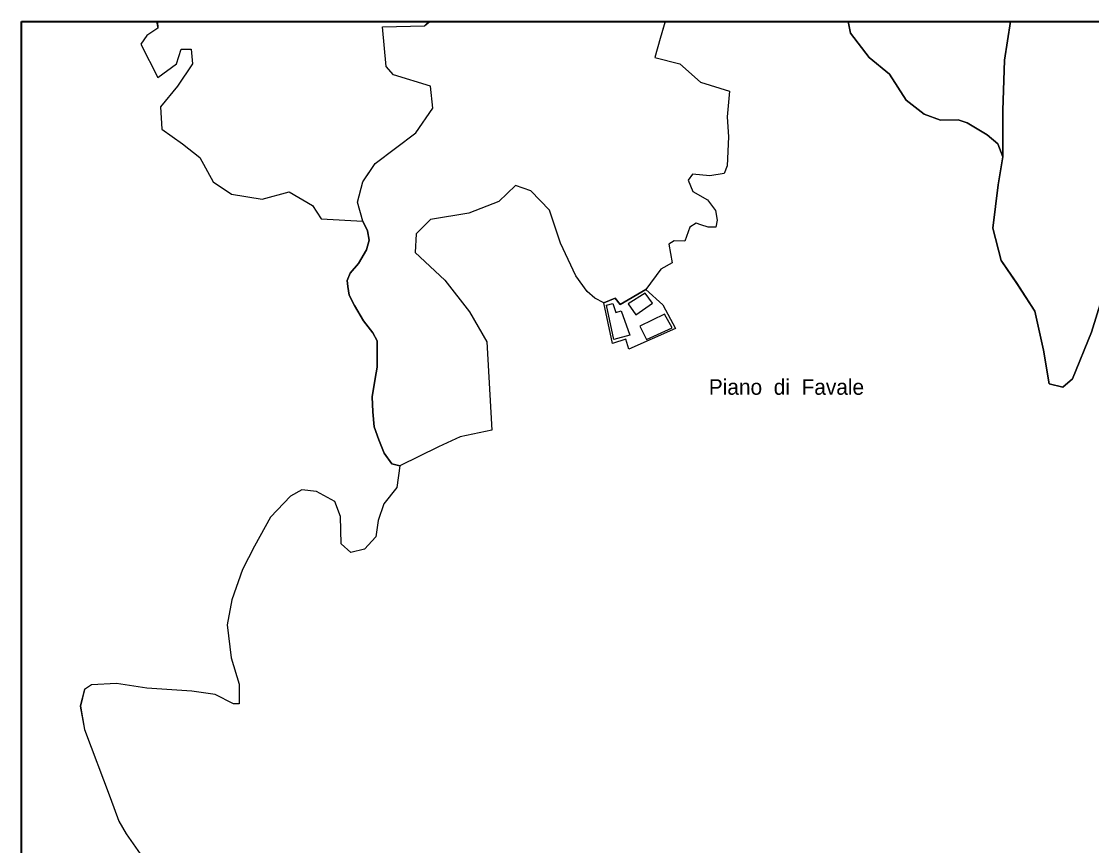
# Model space of a CAD drawing. Extents: x 652791 to 656927, y 889884 to 892405.
# Drawn here: x 654894 to 655580, y 891877 to 892405 of the extents above; entities that cross this region are included whole.
import ezdxf
from ezdxf.enums import TextEntityAlignment as Align

# ---------------------------------------------------------------- set-up
doc = ezdxf.new("R2010")
doc.units = 0
doc.header["$LTSCALE"] = 5.6
for name, color, linetype, lineweight in [('36', 7, 'Continuous', 25), ('37', 7, 'Continuous', 25), ('4', 7, 'Continuous', 25), ('61', 7, 'Continuous', 35)]:
    doc.layers.add(name, color=color, linetype=linetype, lineweight=lineweight)
doc.layers.add('60', color=7, linetype='Continuous')

msp = doc.modelspace()

# ---------------------------------------------------------------- linework, layer by layer
at = {"layer": '36'}
for points in [[(654894.04, 891863.87), (654894.04, 892404.69), (654981.23, 892404.69), (654981.62, 892400.32), (654974.54, 892395.59), (654970.6, 892390.08), (654981.62, 892368.8), (654993.43, 892377.47), (654996.58, 892386.92), (655002.88, 892386.92), (655003.66, 892377.47), (654994.22, 892363.28), (654983.2, 892349.89), (654983.99, 892335.7), (654997.37, 892326.25), (655008.39, 892317.58), (655017.05, 892301.82), (655028.85, 892293.94), (655048.53, 892290.78), (655065.85, 892295.51), (655080.8, 892286.84), (655086.31, 892278.17), (655113.08, 892276.6)], [(655136.81, 892120.01), (655131.7, 892121.2), (655126.73, 892128.09), (655123.28, 892136.52), (655120.22, 892144.94), (655119.46, 892154.52), (655119.07, 892164.09), (655120.99, 892175.96), (655122.14, 892183.24), (655122.14, 892193.58), (655122.14, 892200.09), (655119.46, 892205.07), (655113.33, 892212.73), (655107.59, 892222.69), (655104.15, 892229.2), (655103.38, 892234.94), (655103, 892238.77), (655104.91, 892243.37), (655110.27, 892249.5), (655115.25, 892258.3), (655117.16, 892264.43), (655116.01, 892270.56), (655113.08, 892276.6), (655109.5, 892288.94), (655113.08, 892301.82), (655120.95, 892313.64), (655146.92, 892333.34), (655157.95, 892349.1), (655156.37, 892363.28), (655132.76, 892370.38), (655128.03, 892375.89), (655125.57, 892401.31), (655152.48, 892401.77), (655155.4, 892404.69)], [(655155.4, 892404.69), (655306.84, 892404.69), (655303.61, 892393.8), (655300.24, 892381.51), (655316.29, 892377.54), (655329.56, 892365.85), (655348.08, 892359.9), (655346.61, 892343.64), (655347.6, 892330.75), (655346.61, 892312.11), (655344.63, 892307.34), (655335.47, 892305.7), (655324.42, 892306.75), (655321.65, 892302.98), (655324.62, 892295.64), (655333.93, 892290.29), (655339.09, 892283.55), (655340.27, 892277.4), (655339.48, 892272.84), (655334.53, 892272.84), (655329.83, 892274.43), (655326.74, 892275.43), (655322.61, 892272.93), (655319.52, 892263.92), (655312.73, 892264.11), (655309.21, 892261.92), (655310.24, 892255.92), (655311.27, 892249.92), (655304.05, 892245.92), (655294.4, 892232.82), (655278.02, 892223.22), (655274.79, 892227.38), (655267.64, 892224.38), (655261.8, 892227.43), (655256.91, 892231.7), (655249.68, 892241.57), (655239.83, 892262.62), (655232.6, 892283.68), (655220.77, 892296.18), (655210.91, 892299.47)], [(655589.82, 892404.69), (655528.42, 892404.69), (655524.46, 892379.77), (655523.46, 892347.69), (655523.53, 892317.96), (655520.45, 892300.06), (655517.04, 892272.21), (655522.46, 892251.46), (655532.48, 892236.87), (655543.85, 892219.11), (655549.51, 892194.1), (655553.17, 892172.51), (655561.92, 892170.25), (655568.13, 892175.61), (655580.26, 892205.55), (655590.43, 892238.03)], [(655210.91, 892299.47), (655200.18, 892289.22), (655180.99, 892281.82), (655156.37, 892277.76), (655147.11, 892268.67), (655146.51, 892256.7), (655165.57, 892238.94), (655181.34, 892218.54), (655192.51, 892199.46), (655195.8, 892142.87), (655175.47, 892138.51), (655161.55, 892132.01), (655136.81, 892120.01)], [(655113.08, 892276.6), (655116.01, 892270.56), (655117.16, 892264.43), (655115.25, 892258.3), (655110.27, 892249.5), (655104.91, 892243.37), (655103, 892238.77), (655103.38, 892234.94), (655104.15, 892229.2), (655107.59, 892222.69), (655113.33, 892212.73), (655119.46, 892205.07), (655122.14, 892200.09), (655122.14, 892193.58), (655122.14, 892183.24), (655120.99, 892175.96), (655119.07, 892164.09), (655119.46, 892154.52), (655120.22, 892144.94), (655123.28, 892136.52), (655126.73, 892128.09), (655131.7, 892121.2), (655136.81, 892120.01), (655134.74, 892106), (655126.49, 892095.5), (655122.88, 892084.99), (655121.34, 892074.49), (655114.12, 892066.49), (655105.35, 892064.49), (655099.17, 892069.99), (655098.65, 892087.49), (655095.04, 892097), (655083.18, 892103.5), (655073.9, 892104.5), (655066.68, 892100.5), (655053.79, 892086.99), (655043.48, 892068.49), (655035.75, 892053.48), (655029.05, 892033.98), (655025.95, 892017.97)], [(655025.95, 892017.97), (655028.53, 891996.96), (655033.69, 891979.96), (655033.69, 891967.45), (655030.08, 891967.45), (655018.22, 891973.45), (655003.27, 891975.45), (654974.39, 891977.45), (654955.03, 891980.52), (654939.05, 891979.52), (654934.41, 891976.52), (654931.83, 891966.02), (654934.41, 891951.01), (654950.9, 891907.5), (654956.59, 891892.22), (654961.23, 891884.22), (654977.73, 891860.71)]]:
    msp.add_lwpolyline(points, dxfattribs=at)
at = {"layer": '37'}
for points in [[(655155.91, 892404.69), (654980.62, 892404.69), (654981.63, 892400.32), (654974.55, 892395.59), (654970.61, 892390.08), (654981.63, 892368.8), (654993.44, 892377.47), (654996.59, 892386.92), (655002.89, 892386.92), (655003.67, 892377.47), (654994.23, 892363.28), (654983.21, 892349.89), (654984, 892335.7), (654997.38, 892326.25), (655008.4, 892317.58), (655017.06, 892301.82), (655028.86, 892293.94), (655048.54, 892290.78), (655065.86, 892295.51), (655080.81, 892286.84), (655086.32, 892278.17), (655113.08, 892276.6)], [(655113.08, 892276.6), (655109.5, 892288.94), (655113.08, 892301.82), (655117.92, 892309.08), (655120.95, 892313.64), (655146.92, 892333.34), (655157.95, 892349.1), (655156.37, 892363.28), (655132.76, 892370.38), (655128.03, 892375.89), (655125.57, 892401.31), (655152.48, 892401.77), (655155.91, 892404.69)], [(655424.27, 892404.69), (655306.84, 892404.69), (655306.66, 892404.1), (655303.61, 892393.8), (655300.24, 892381.51), (655316.29, 892377.54), (655329.56, 892365.85), (655348.08, 892359.9), (655346.61, 892343.64), (655347.6, 892330.75), (655346.61, 892312.11), (655344.63, 892307.34), (655335.47, 892305.7), (655324.42, 892306.75), (655321.65, 892302.98), (655324.62, 892295.64), (655333.93, 892290.29), (655339.09, 892283.55), (655340.27, 892277.4), (655339.48, 892272.84), (655334.53, 892272.84), (655329.83, 892274.43), (655326.74, 892275.43), (655322.61, 892272.93), (655319.52, 892263.92), (655312.73, 892264.11), (655309.21, 892261.92), (655310.24, 892255.92), (655311.27, 892249.92), (655304.05, 892245.92), (655294.4, 892232.82)], [(655520.14, 892326.19), (655513.43, 892332.12), (655500.54, 892339.61), (655494.87, 892341.67), (655483.52, 892341.41), (655472.95, 892345.28), (655461.34, 892354.31), (655450.65, 892370.83), (655437.8, 892381.55), (655425.66, 892397.27), (655424.27, 892404.69)], [(655528.42, 892404.69), (655424.27, 892404.69), (655425.66, 892397.27), (655437.8, 892381.55), (655450.65, 892370.83)], [(655450.65, 892370.83), (655461.34, 892354.31), (655472.95, 892345.28), (655483.52, 892341.41), (655494.87, 892341.67), (655500.54, 892339.61), (655513.43, 892332.12), (655520.14, 892326.19), (655523.53, 892317.96), (655523.46, 892347.69), (655524.46, 892379.77), (655528.42, 892404.69)], [(655590.43, 892238.02), (655580.26, 892205.54), (655568.13, 892175.6), (655561.92, 892170.24), (655553.17, 892172.5), (655549.51, 892194.09), (655543.85, 892219.1), (655532.48, 892236.86), (655522.46, 892251.45), (655517.04, 892272.2), (655520.45, 892300.05), (655523.53, 892317.95), (655520.14, 892326.19)], [(655294.4, 892232.82), (655305.47, 892223.02), (655313.52, 892207.99), (655283.61, 892194.75), (655281.64, 892201), (655273.09, 892198.37), (655267.64, 892224.38), (655261.8, 892227.43), (655256.91, 892231.7), (655249.68, 892241.57), (655239.83, 892262.62), (655232.6, 892283.68), (655220.77, 892296.18), (655210.91, 892299.47), (655200.18, 892289.22), (655181, 892281.81), (655156.37, 892277.76), (655147.11, 892268.67), (655146.51, 892256.7), (655165.57, 892238.94), (655181.34, 892218.54), (655192.51, 892199.46), (655195.8, 892142.87), (655175.47, 892138.51), (655161.55, 892132.01), (655136.81, 892120.01), (655134.75, 892106), (655126.5, 892095.5), (655122.89, 892084.99), (655121.35, 892074.49), (655114.13, 892066.49), (655105.36, 892064.49), (655099.18, 892069.99), (655098.66, 892087.49), (655095.05, 892097), (655083.19, 892103.5), (655073.91, 892104.5), (655066.69, 892100.5), (655053.8, 892086.99), (655043.49, 892068.49)], [(655043.49, 892068.49), (655035.76, 892053.48), (655029.06, 892033.98), (655025.96, 892017.97), (655028.54, 891996.96), (655033.7, 891979.96), (655033.7, 891967.45), (655030.09, 891967.45), (655018.23, 891973.45), (655003.28, 891975.45), (654974.4, 891977.45), (654955.04, 891980.52), (654939.06, 891979.52), (654934.42, 891976.52), (654931.84, 891966.02), (654934.42, 891951.01), (654950.91, 891907.5), (654956.6, 891892.22), (654961.24, 891884.22), (654977.74, 891860.71)]]:
    msp.add_lwpolyline(points, dxfattribs=at)
at = {"layer": '4'}
for points in [[(655313.52, 892207.99), (655283.61, 892194.75), (655281.64, 892201), (655273.09, 892198.37), (655267.64, 892224.38), (655274.79, 892227.38), (655278.02, 892223.22), (655294.4, 892232.82)], [(655294.4, 892232.82), (655305.47, 892223.02), (655313.52, 892207.99)]]:
    msp.add_lwpolyline(points, dxfattribs=at)
for points in [[(655293.98, 892230.55), (655283.05, 892223.67), (655288.11, 892216.66), (655298.74, 892224.06)], [(655269.16, 892222.83), (655273.32, 892223.9), (655275.32, 892218.26), (655278.71, 892219.16), (655284.24, 892203.69), (655274.03, 892200.84)], [(655306.53, 892217.05), (655290.54, 892209.4), (655294.85, 892200.96), (655311.32, 892208.45)]]:
    msp.add_lwpolyline(points, close=True, dxfattribs=at)
at = {"layer": '61', "lineweight": 40}
msp.add_lwpolyline([(654894.04, 892404.68), (656926.84, 892404.68), (656926.84, 889884.41), (654894.04, 889884.41)], close=True, dxfattribs=at)

# ---------------------------------------------------------------- texts
at = {"layer": '60'}
msp.add_text('Piano  di  Favale', height=10, dxfattribs=at).set_placement((655384.67, 892165.45), align=Align.CENTER)

doc.saveas('drawing.dxf')
